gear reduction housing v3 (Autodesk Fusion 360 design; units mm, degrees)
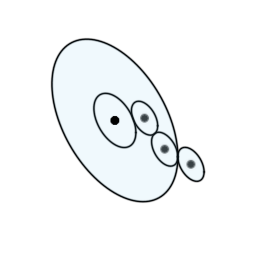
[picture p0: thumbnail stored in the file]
parameter "Drive_Gear_Dia" = 96 (= "( ( Drive_Gear_Teeth * Gear_Module ) * 1 mm )")
parameter "Driven_Gear_Dia" = 32 (= "( ( Driven_Gear_Teeth * Gear_Module ) * 1 mm )")
parameter "Idle_Gear_Dia" = 20 (= "( ( Idle_Gear_Teeth * Gear_Module ) * 1 mm )")
parameter "Mount_Bolts" = 8
parameter "Idle_Gear_Shaft" = 8
parameter "Mount_Bolt_Flange" = 12
parameter "Gear_Clearance_Dia" = 4
sketch "Layout Sketch" plane through (0, 0, 0) normal (0, 0, 1) x axis (1, 0, 0)
  circle C1 centre (0, 0) radius 48
  circle C2 centre (0, 0) radius 16
  circle C3 centre (22.6316, 12.7989) radius 10
  circle C4 centre (38, 0) radius 10
  circle C5 centre (58, 0) radius 10
  point P1 (0, 0)
  point P2 (0, 0)
  point P3 (0, 0)
  point P6 (58, 0)
  point P5 (38, 0)
  coincident P1 P2
  coincident P1 P3
  equal C4 C5
  equal C3 C4
  horizontal P1 P6
  tangent C1 C5
  tangent C1 C4
  tangent C3 C4
  tangent C2 C3
  horizontal P5 P6
  dimension "d8" diameter C1 = 96 (= "Drive_Gear_Dia")
  dimension "d9" diameter C2 = 32 (= "Driven_Gear_Dia")
  dimension "d10" diameter C5 = 20 (= "Idle_Gear_Dia")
